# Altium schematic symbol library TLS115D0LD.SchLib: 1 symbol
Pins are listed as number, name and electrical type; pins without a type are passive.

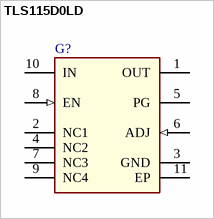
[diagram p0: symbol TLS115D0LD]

## TLS115D0LD
designator G?  (value not drawn)
Monolithic Integrated Low-Dropout Voltage Tracking Regulator; Manufacturer: Infineon Technologies
footprint SON50P330X330X110-11N
pins: 1 OUT (power) "Tracker Output", 2 NC1 "Not Connected", 3 GND (power) "Ground", 4 NC2 "Not Connected", 5 PG (oc) "Power Good ,Open collector output", 6 ADJ (in) "Adjust", 7 NC3 "Not Connected", 8 EN (in) "Enable", 9 NC4 "No Connected", 10 IN (power) "Input", 11 EP (power) "Exposed Pad"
